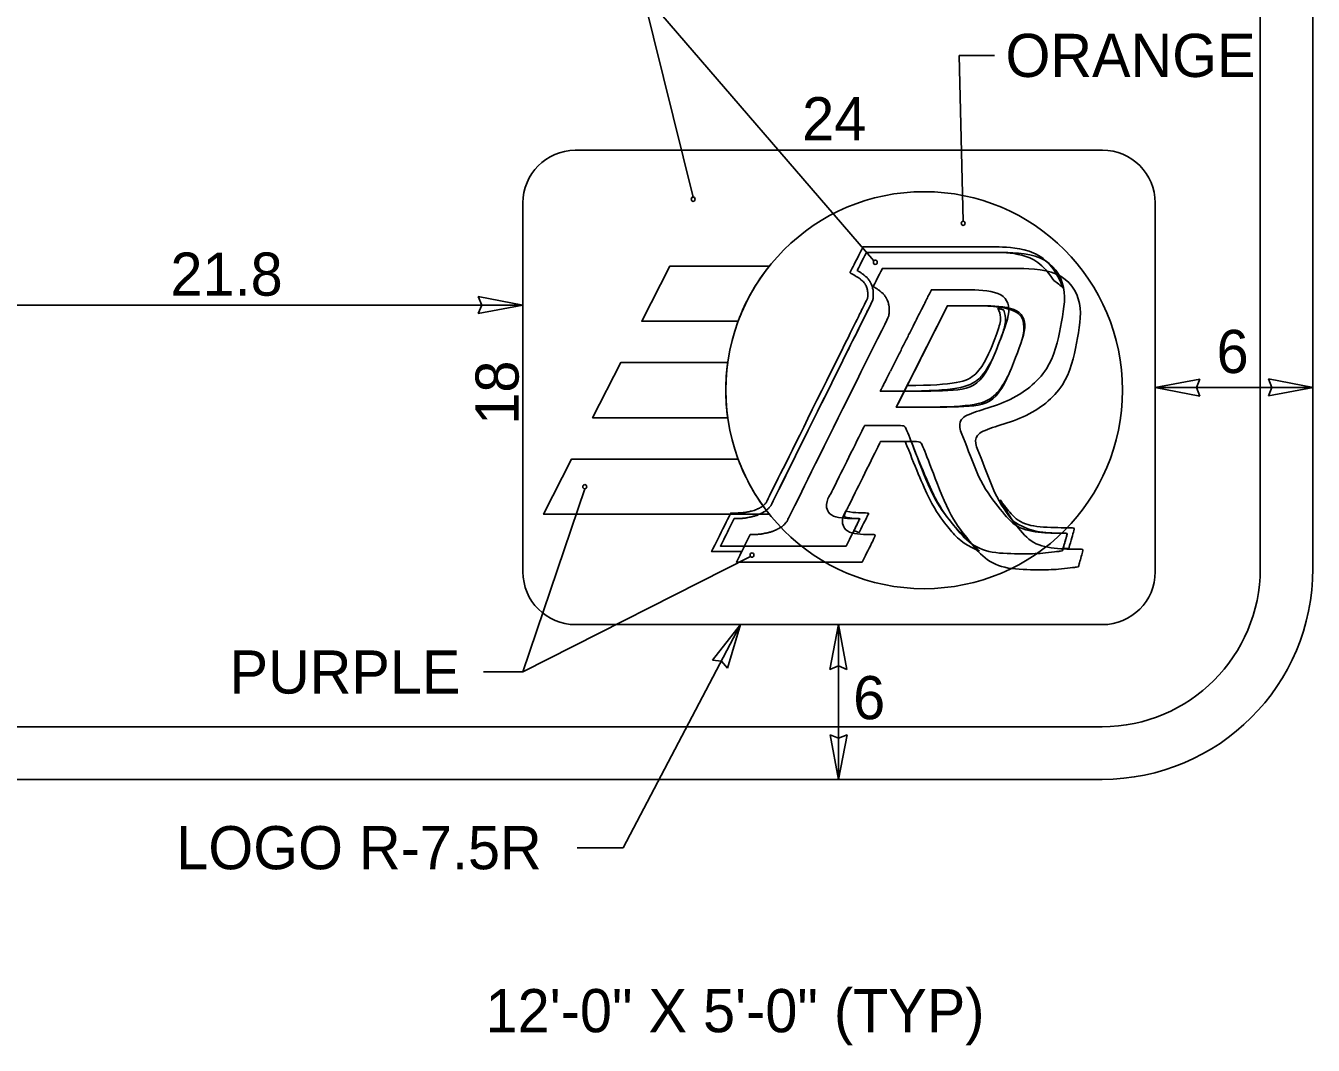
# Model space of a CAD drawing. Extents: x 319706 to 320449, y 1621775 to 1622117.
# Drawn here: x 320236.54 to 320278.32, y 1621842.48 to 1621875.55 of the extents above; entities that cross this region are included whole.
import ezdxf

# ---------------------------------------------------------------- set-up
doc = ezdxf.new("R2010")
doc.units = 0
for name, color, linetype in [('1', 7, 'Continuous'), ('52', 7, 'Continuous'), ('SignPanel', 7, 'Continuous')]:
    doc.layers.add(name, color=color, linetype=linetype)

msp = doc.modelspace()

# ---------------------------------------------------------------- linework, layer by layer
at = {"layer": '1'}
for p, q in [((320256.542, 1621876.645), (320258.197, 1621869.995)), ((320264.062, 1621867.926), (320256.542, 1621876.645)), ((320266.827, 1621874.588), (320267.975, 1621874.588)), ((320266.827, 1621874.588), (320266.96, 1621869.215)), ((320273.193, 1621863.82), (320278.323, 1621863.82)), ((320252.673, 1621854.589), (320254.68, 1621860.527)), ((320252.673, 1621854.589), (320260.06, 1621858.332)), ((320259.738, 1621856.125), (320255.927, 1621848.888)), ((320262.911, 1621851.105), (320262.911, 1621856.125)), ((320251.39, 1621854.589), (320252.673, 1621854.589)), ((320254.43, 1621848.888), (320255.927, 1621848.888))]:
    msp.add_line(p, q, dxfattribs=at)
for centre in [(320258.197, 1621869.924), (320266.96, 1621869.144), (320264.109, 1621867.877), (320254.68, 1621860.598), (320260.107, 1621858.381)]:
    msp.add_ellipse(centre, major_axis=(0, 0.0707), ratio=0.906668, dxfattribs=at)
at = {"layer": '52'}
for p, q in [((320252.673, 1621866.484), (320251.223, 1621866.764)), ((320251.223, 1621866.764), (320251.333, 1621866.484)), ((320251.333, 1621866.484), (320251.223, 1621866.214)), ((320251.223, 1621866.214), (320252.673, 1621866.484)), ((320274.643, 1621864.09), (320273.193, 1621863.82)), ((320274.533, 1621863.82), (320274.643, 1621864.09)), ((320278.323, 1621863.82), (320276.873, 1621864.1)), ((320276.873, 1621864.1), (320276.983, 1621863.82)), ((320273.193, 1621863.82), (320274.643, 1621863.54)), ((320274.643, 1621863.54), (320274.533, 1621863.82)), ((320276.983, 1621863.82), (320276.873, 1621863.55)), ((320276.873, 1621863.55), (320278.323, 1621863.82)), ((320258.824, 1621854.968), (320259.738, 1621856.125)), ((320259.738, 1621856.125), (320259.31, 1621854.712)), ((320262.911, 1621856.125), (320262.631, 1621854.675)), ((320263.181, 1621854.675), (320262.911, 1621856.125)), ((320259.114, 1621854.94), (320258.824, 1621854.968)), ((320259.31, 1621854.712), (320259.114, 1621854.94)), ((320262.631, 1621854.675), (320262.911, 1621854.785)), ((320262.911, 1621854.785), (320263.181, 1621854.675)), ((320262.911, 1621852.445), (320262.641, 1621852.555)), ((320262.641, 1621852.555), (320262.911, 1621851.105)), ((320262.911, 1621851.105), (320263.191, 1621852.555)), ((320263.191, 1621852.555), (320262.911, 1621852.445))]:
    msp.add_line(p, q, dxfattribs=at)
at = {"layer": 'SignPanel'}
for p, q in [((320276.602, 1621895.565), (320276.602, 1621857.945)), ((320278.312, 1621857.945), (320278.312, 1621895.565)), ((320254.363, 1621871.514), (320271.481, 1621871.514)), ((320252.673, 1621857.834), (320252.673, 1621869.805)), ((320273.193, 1621869.805), (320273.193, 1621857.834)), ((320252.673, 1621866.484), (320234.021, 1621866.484)), ((320263.056, 1621865.095), (320263.063, 1621865.11)), ((320263.223, 1621865.03), (320263.216, 1621865.015)), ((320265.273, 1621862.064), (320265.081, 1621862.064)), ((320259.862, 1621858.674), (320259.772, 1621858.496)), ((320271.481, 1621856.125), (320254.384, 1621856.125)), ((320271.472, 1621852.815), (320162.048, 1621852.815)), ((320162.048, 1621851.105), (320271.472, 1621851.105))]:
    msp.add_line(p, q, dxfattribs=at)
for points in [[(320260.669, 1621867.754), (320257.441, 1621867.754), (320256.53, 1621865.965), (320259.657, 1621865.965)], [(320267.307, 1621866.47), (320266.451, 1621866.47), (320264.789, 1621863.177), (320265.334, 1621863.177)], [(320259.319, 1621864.623), (320255.846, 1621864.623), (320254.934, 1621862.834), (320259.319, 1621862.834)], [(320259.657, 1621861.493), (320254.251, 1621861.493), (320253.34, 1621859.704), (320260.67, 1621859.704)]]:
    msp.add_lwpolyline(points, dxfattribs=at)
msp.add_circle((320265.695, 1621863.729), 6.438, dxfattribs=at)
for centre, radius, start, end in [((320254.382, 1621869.804), 1.71, 90.6597, 180), ((320271.481, 1621869.804), 1.71, 0, 90), ((320265.695, 1621863.729), 6.438, 141.3093, 159.6812), ((320268.931, 1621865.787), 1.786, 44.1751, 57.1095), ((320265.695, 1621863.729), 6.438, 172.0148, 187.9874), ((320265.695, 1621863.729), 6.438, 200.3256, 218.6989), ((320273.791, 1621863.128), 6.357, 207.7086, 215.0356), ((320263.593, 1621859.594), 0.486, 153.9516, 176.8436), ((320263.861, 1621860.105), 1.029, 244.3445, 254.3668), ((320269.318, 1621860.665), 2.825, 217.4324, 229.8152), ((320270.747, 1621863.158), 4.583, 263.2057, 265.4782), ((320254.382, 1621857.835), 1.71, 180, 270), ((320271.472, 1621857.945), 6.84, 270, 0), ((320271.472, 1621857.945), 5.13, 270, 0), ((320271.481, 1621857.835), 1.71, 270, 360)]:
    msp.add_arc(centre, radius, start, end, dxfattribs=at)
for points, degree in [([(320263.759, 1621862.583), (320263.759, 1621862.583), (320262.666, 1621860.376), (320262.666, 1621860.376), (320262.468, 1621860.054), (320262.61, 1621859.567), (320263.61, 1621859.567), (320263.61, 1621859.567), (320263.164, 1621858.674), (320263.164, 1621858.674), (320263.164, 1621858.674), (320259.084, 1621858.674), (320259.084, 1621858.674), (320259.084, 1621858.674), (320259.53, 1621859.567), (320259.53, 1621859.567), (320259.53, 1621859.567), (320259.657, 1621859.567), (320259.657, 1621859.567), (320259.657, 1621859.567), (320259.795, 1621859.573), (320259.795, 1621859.573), (320259.795, 1621859.573), (320259.91, 1621859.585), (320259.91, 1621859.585), (320259.91, 1621859.585), (320260.109, 1621859.627), (320260.109, 1621859.627), (320260.109, 1621859.627), (320260.26, 1621859.669), (320260.26, 1621859.669), (320260.26, 1621859.669), (320260.386, 1621859.724), (320260.386, 1621859.724), (320260.386, 1621859.724), (320260.477, 1621859.772), (320260.477, 1621859.772), (320260.477, 1621859.772), (320260.567, 1621859.826), (320260.567, 1621859.826), (320260.567, 1621859.826), (320260.658, 1621859.911), (320260.658, 1621859.911), (320260.658, 1621859.911), (320260.724, 1621859.995), (320260.724, 1621859.995), (320260.724, 1621859.995), (320260.748, 1621860.043), (320260.748, 1621860.043), (320260.748, 1621860.043), (320264.029, 1621866.653), (320264.029, 1621866.653), (320264.029, 1621866.653), (320264.041, 1621866.749), (320264.041, 1621866.749), (320264.041, 1621866.749), (320264.041, 1621866.839), (320264.041, 1621866.839), (320264.041, 1621866.839), (320264.041, 1621866.906), (320264.041, 1621866.906), (320264.041, 1621866.906), (320264.035, 1621866.99), (320264.035, 1621866.99), (320264.035, 1621866.99), (320264.01, 1621867.093), (320264.01, 1621867.093), (320264.01, 1621867.093), (320263.968, 1621867.201), (320263.968, 1621867.201), (320263.968, 1621867.201), (320263.926, 1621867.273), (320263.926, 1621867.273), (320263.926, 1621867.273), (320263.847, 1621867.376), (320263.847, 1621867.376), (320263.847, 1621867.376), (320263.739, 1621867.467), (320263.739, 1621867.467), (320263.739, 1621867.467), (320263.631, 1621867.545), (320263.631, 1621867.545), (320263.631, 1621867.545), (320263.522, 1621867.611), (320263.522, 1621867.611), (320263.522, 1621867.611), (320263.818, 1621868.196), (320263.818, 1621868.196), (320263.818, 1621868.196), (320267.829, 1621868.196), (320267.829, 1621868.196), (320269.65, 1621868.196), (320270.38, 1621867.092), (320270.125, 1621865.8), (320269.842, 1621864.369), (320268.469, 1621863.249), (320266.6, 1621862.922), (320267.009, 1621862.159), (320267.498, 1621860.697), (320268.197, 1621859.826), (320268.672, 1621859.234), (320269.499, 1621859.09), (320270.343, 1621859.09), (320270.343, 1621859.09), (320270.18, 1621858.519), (320270.18, 1621858.519), (320270.18, 1621858.519), (320270.068, 1621858.503), (320270.068, 1621858.503), (320269.604, 1621858.441), (320269.306, 1621858.425), (320268.963, 1621858.425), (320267.827, 1621858.425), (320267.129, 1621858.752), (320266.593, 1621859.421), (320265.968, 1621860.199), (320265.365, 1621861.856), (320265.064, 1621862.583), (320265.064, 1621862.583), (320263.759, 1621862.583), (320263.759, 1621862.583)], 3), ([(320263.063, 1621865.11), (320263.526, 1621866.043), (320263.855, 1621866.705), (320263.855, 1621866.705), (320263.855, 1621866.705), (320263.862, 1621866.76), (320263.862, 1621866.76), (320263.862, 1621866.76), (320263.862, 1621866.839), (320263.862, 1621866.839), (320263.862, 1621866.839), (320263.862, 1621866.899), (320263.862, 1621866.899), (320263.862, 1621866.899), (320263.857, 1621866.963), (320263.857, 1621866.963), (320263.857, 1621866.963), (320263.839, 1621867.04), (320263.839, 1621867.04), (320263.839, 1621867.04), (320263.807, 1621867.123), (320263.807, 1621867.123), (320263.807, 1621867.123), (320263.777, 1621867.173), (320263.777, 1621867.173), (320263.777, 1621867.173), (320263.717, 1621867.252), (320263.717, 1621867.252), (320263.717, 1621867.252), (320263.629, 1621867.325), (320263.629, 1621867.325), (320263.629, 1621867.325), (320263.532, 1621867.396), (320263.532, 1621867.396), (320263.532, 1621867.396), (320263.288, 1621867.544), (320263.288, 1621867.544), (320263.288, 1621867.544), (320263.708, 1621868.375), (320263.708, 1621868.375), (320263.708, 1621868.375), (320267.829, 1621868.375), (320267.829, 1621868.375), (320269.116, 1621868.375), (320269.91, 1621867.814), (320270.212, 1621867.032)], 3), ([(320263.223, 1621865.03), (320263.686, 1621865.963), (320264.029, 1621866.653), (320264.029, 1621866.653), (320264.029, 1621866.653), (320264.041, 1621866.749), (320264.041, 1621866.749), (320264.041, 1621866.749), (320264.041, 1621866.839), (320264.041, 1621866.839), (320264.041, 1621866.839), (320264.041, 1621866.906), (320264.041, 1621866.906), (320264.041, 1621866.906), (320264.035, 1621866.99), (320264.035, 1621866.99), (320264.035, 1621866.99), (320264.01, 1621867.093), (320264.01, 1621867.093), (320264.01, 1621867.093), (320263.968, 1621867.201), (320263.968, 1621867.201), (320263.968, 1621867.201), (320263.926, 1621867.273), (320263.926, 1621867.273), (320263.926, 1621867.273), (320263.847, 1621867.376), (320263.847, 1621867.376), (320263.847, 1621867.376), (320263.739, 1621867.467), (320263.739, 1621867.467), (320263.739, 1621867.467), (320263.631, 1621867.545), (320263.631, 1621867.545), (320263.631, 1621867.545), (320263.522, 1621867.611), (320263.522, 1621867.611), (320263.522, 1621867.611), (320263.818, 1621868.196), (320263.818, 1621868.196), (320263.818, 1621868.196), (320267.829, 1621868.196), (320267.829, 1621868.196), (320269.65, 1621868.196), (320270.38, 1621867.092), (320270.125, 1621865.8), (320269.842, 1621864.369), (320268.469, 1621863.249), (320266.6, 1621862.922), (320267.009, 1621862.159), (320267.498, 1621860.697), (320268.197, 1621859.826), (320268.672, 1621859.234), (320269.499, 1621859.09), (320270.343, 1621859.09), (320270.343, 1621859.09), (320270.18, 1621858.519), (320270.18, 1621858.519), (320270.18, 1621858.519), (320270.068, 1621858.503), (320270.068, 1621858.503), (320269.604, 1621858.441), (320269.306, 1621858.425), (320268.963, 1621858.425), (320267.827, 1621858.425), (320267.129, 1621858.752), (320266.593, 1621859.421), (320265.968, 1621860.199), (320265.365, 1621861.856), (320265.064, 1621862.583), (320265.064, 1621862.583), (320263.759, 1621862.583), (320263.759, 1621862.583)], 3), ([(320269.901, 1621867.287), (320269.552, 1621867.836), (320268.868, 1621868.196), (320267.829, 1621868.196), (320267.829, 1621868.196), (320263.818, 1621868.196), (320263.818, 1621868.196), (320263.818, 1621868.196), (320263.522, 1621867.611), (320263.522, 1621867.611), (320263.522, 1621867.611), (320263.631, 1621867.545), (320263.631, 1621867.545), (320263.631, 1621867.545), (320263.739, 1621867.467), (320263.739, 1621867.467), (320263.739, 1621867.467), (320263.847, 1621867.376), (320263.847, 1621867.376), (320263.847, 1621867.376), (320263.926, 1621867.273), (320263.926, 1621867.273), (320263.926, 1621867.273), (320263.968, 1621867.201), (320263.968, 1621867.201), (320263.968, 1621867.201), (320264.01, 1621867.093), (320264.01, 1621867.093), (320264.01, 1621867.093), (320264.035, 1621866.99), (320264.035, 1621866.99), (320264.035, 1621866.99), (320264.041, 1621866.906), (320264.041, 1621866.906), (320264.041, 1621866.906), (320264.041, 1621866.839), (320264.041, 1621866.839), (320264.041, 1621866.839), (320264.041, 1621866.749), (320264.041, 1621866.749), (320264.041, 1621866.749), (320264.029, 1621866.653), (320264.029, 1621866.653), (320264.029, 1621866.653), (320263.686, 1621865.963), (320263.223, 1621865.03)], 3), ([(320264.278, 1621862.064), (320264.278, 1621862.064), (320263.185, 1621859.858), (320263.185, 1621859.858), (320262.986, 1621859.536), (320263.129, 1621859.048), (320264.129, 1621859.048), (320264.129, 1621859.048), (320263.683, 1621858.156), (320263.683, 1621858.156), (320263.683, 1621858.156), (320259.602, 1621858.156), (320259.602, 1621858.156), (320259.602, 1621858.156), (320260.049, 1621859.048), (320260.049, 1621859.048), (320260.049, 1621859.048), (320260.175, 1621859.048), (320260.175, 1621859.048), (320260.175, 1621859.048), (320260.314, 1621859.055), (320260.314, 1621859.055), (320260.314, 1621859.055), (320260.428, 1621859.066), (320260.428, 1621859.066), (320260.428, 1621859.066), (320260.628, 1621859.108), (320260.628, 1621859.108), (320260.628, 1621859.108), (320260.778, 1621859.151), (320260.778, 1621859.151), (320260.778, 1621859.151), (320260.905, 1621859.205), (320260.905, 1621859.205), (320260.905, 1621859.205), (320260.995, 1621859.253), (320260.995, 1621859.253), (320260.995, 1621859.253), (320261.086, 1621859.308), (320261.086, 1621859.308), (320261.086, 1621859.308), (320261.176, 1621859.392), (320261.176, 1621859.392), (320261.176, 1621859.392), (320261.243, 1621859.476), (320261.243, 1621859.476), (320261.243, 1621859.476), (320261.266, 1621859.525), (320261.266, 1621859.525), (320261.266, 1621859.525), (320264.547, 1621866.134), (320264.547, 1621866.134), (320264.547, 1621866.134), (320264.559, 1621866.23), (320264.559, 1621866.23), (320264.559, 1621866.23), (320264.559, 1621866.32), (320264.559, 1621866.32), (320264.559, 1621866.32), (320264.559, 1621866.387), (320264.559, 1621866.387), (320264.559, 1621866.387), (320264.553, 1621866.471), (320264.553, 1621866.471), (320264.553, 1621866.471), (320264.529, 1621866.574), (320264.529, 1621866.574), (320264.529, 1621866.574), (320264.487, 1621866.683), (320264.487, 1621866.683), (320264.487, 1621866.683), (320264.445, 1621866.755), (320264.445, 1621866.755), (320264.445, 1621866.755), (320264.366, 1621866.858), (320264.366, 1621866.858), (320264.366, 1621866.858), (320264.258, 1621866.948), (320264.258, 1621866.948), (320264.258, 1621866.948), (320264.149, 1621867.026), (320264.149, 1621867.026), (320264.149, 1621867.026), (320264.041, 1621867.092), (320264.041, 1621867.092), (320264.041, 1621867.092), (320264.336, 1621867.678), (320264.336, 1621867.678), (320264.336, 1621867.678), (320268.348, 1621867.678), (320268.348, 1621867.678), (320270.168, 1621867.678), (320270.899, 1621866.573), (320270.644, 1621865.281), (320270.361, 1621863.85), (320268.988, 1621862.73), (320267.119, 1621862.403), (320267.528, 1621861.641), (320268.017, 1621860.178), (320268.716, 1621859.307), (320269.191, 1621858.716), (320270.018, 1621858.571), (320270.862, 1621858.571), (320270.862, 1621858.571), (320270.698, 1621858), (320270.698, 1621858), (320270.698, 1621858), (320270.586, 1621857.984), (320270.586, 1621857.984), (320270.123, 1621857.922), (320269.824, 1621857.907), (320269.482, 1621857.907), (320268.346, 1621857.907), (320267.648, 1621858.233), (320267.111, 1621858.902), (320266.487, 1621859.68), (320265.884, 1621861.338), (320265.583, 1621862.064), (320265.583, 1621862.064), (320264.278, 1621862.064), (320264.278, 1621862.064)], 3), ([(320264.592, 1621864.332), (320264.402, 1621863.957), (320264.27, 1621863.696), (320264.27, 1621863.696), (320264.27, 1621863.696), (320264.815, 1621863.696), (320264.815, 1621863.696), (320266.604, 1621863.696), (320267.57, 1621863.828), (320268.171, 1621865.384), (320268.588, 1621866.462), (320268.126, 1621866.988), (320266.788, 1621866.988), (320266.788, 1621866.988), (320265.932, 1621866.988), (320265.932, 1621866.988)], 3), ([(320265.932, 1621866.988), (320265.932, 1621866.988), (320265.083, 1621865.307), (320264.599, 1621864.347)], 2), ([(320266.451, 1621866.47), (320266.451, 1621866.47), (320264.789, 1621863.177), (320264.789, 1621863.177), (320264.789, 1621863.177), (320265.334, 1621863.177), (320265.334, 1621863.177), (320267.123, 1621863.177), (320268.088, 1621863.309), (320268.69, 1621864.865), (320269.107, 1621865.943), (320268.645, 1621866.47), (320267.307, 1621866.47), (320267.307, 1621866.47), (320266.451, 1621866.47), (320266.451, 1621866.47)], 3), ([(320265.142, 1621863.877), (320266.699, 1621863.895), (320267.477, 1621864.083), (320268.004, 1621865.448), (320268.165, 1621865.863), (320268.196, 1621866.171), (320268.084, 1621866.388)], 3), ([(320265.334, 1621863.177), (320267.123, 1621863.177), (320268.088, 1621863.309), (320268.69, 1621864.865), (320269.107, 1621865.943), (320268.645, 1621866.47), (320267.307, 1621866.47)], 3), ([(320268.084, 1621866.388), (320268.155, 1621866.369), (320268.222, 1621866.348), (320268.283, 1621866.323)], 2), ([(320268.283, 1621866.323), (320268.356, 1621866.079), (320268.319, 1621865.766), (320268.171, 1621865.384), (320267.597, 1621863.898), (320266.69, 1621863.711), (320265.051, 1621863.697)], 3), ([(320259.772, 1621858.496), (320259.202, 1621858.496), (320258.794, 1621858.496), (320258.794, 1621858.496), (320258.794, 1621858.496), (320259.419, 1621859.746), (320259.419, 1621859.746), (320259.419, 1621859.746), (320259.652, 1621859.746), (320259.652, 1621859.746), (320259.652, 1621859.746), (320259.782, 1621859.752), (320259.782, 1621859.752), (320259.782, 1621859.752), (320259.882, 1621859.762), (320259.882, 1621859.762), (320259.882, 1621859.762), (320260.066, 1621859.801), (320260.066, 1621859.801), (320260.066, 1621859.801), (320260.2, 1621859.838), (320260.2, 1621859.838), (320260.2, 1621859.838), (320260.308, 1621859.885), (320260.308, 1621859.885), (320260.308, 1621859.885), (320260.389, 1621859.928), (320260.389, 1621859.928), (320260.389, 1621859.928), (320260.459, 1621859.97), (320260.459, 1621859.97), (320260.459, 1621859.97), (320260.526, 1621860.032), (320260.526, 1621860.032), (320260.526, 1621860.032), (320260.572, 1621860.091), (320260.572, 1621860.091), (320260.572, 1621860.091), (320260.587, 1621860.122), (320260.587, 1621860.122), (320260.587, 1621860.122), (320262.084, 1621863.137), (320263.056, 1621865.095)], 3), ([(320263.759, 1621862.583), (320263.759, 1621862.583), (320262.666, 1621860.376), (320262.666, 1621860.376), (320262.468, 1621860.054), (320262.61, 1621859.567), (320263.61, 1621859.567), (320263.61, 1621859.567), (320263.164, 1621858.674), (320263.164, 1621858.674), (320263.164, 1621858.674), (320259.084, 1621858.674), (320259.084, 1621858.674), (320259.084, 1621858.674), (320259.53, 1621859.567), (320259.53, 1621859.567), (320259.53, 1621859.567), (320259.657, 1621859.567), (320259.657, 1621859.567), (320259.657, 1621859.567), (320259.795, 1621859.573), (320259.795, 1621859.573), (320259.795, 1621859.573), (320259.91, 1621859.585), (320259.91, 1621859.585), (320259.91, 1621859.585), (320260.109, 1621859.627), (320260.109, 1621859.627), (320260.109, 1621859.627), (320260.26, 1621859.669), (320260.26, 1621859.669), (320260.26, 1621859.669), (320260.386, 1621859.724), (320260.386, 1621859.724), (320260.386, 1621859.724), (320260.477, 1621859.772), (320260.477, 1621859.772), (320260.477, 1621859.772), (320260.567, 1621859.826), (320260.567, 1621859.826), (320260.567, 1621859.826), (320260.658, 1621859.911), (320260.658, 1621859.911), (320260.658, 1621859.911), (320260.724, 1621859.995), (320260.724, 1621859.995), (320260.724, 1621859.995), (320260.748, 1621860.043), (320260.748, 1621860.043), (320260.748, 1621860.043), (320262.244, 1621863.058), (320263.216, 1621865.015)], 3), ([(320263.216, 1621865.015), (320262.244, 1621863.058), (320260.748, 1621860.043), (320260.748, 1621860.043), (320260.748, 1621860.043), (320260.724, 1621859.995), (320260.724, 1621859.995), (320260.724, 1621859.995), (320260.658, 1621859.911), (320260.658, 1621859.911), (320260.658, 1621859.911), (320260.567, 1621859.826), (320260.567, 1621859.826), (320260.567, 1621859.826), (320260.477, 1621859.772), (320260.477, 1621859.772), (320260.477, 1621859.772), (320260.386, 1621859.724), (320260.386, 1621859.724), (320260.386, 1621859.724), (320260.26, 1621859.669), (320260.26, 1621859.669), (320260.26, 1621859.669), (320260.109, 1621859.627), (320260.109, 1621859.627), (320260.109, 1621859.627), (320259.91, 1621859.585), (320259.91, 1621859.585), (320259.91, 1621859.585), (320259.795, 1621859.573), (320259.795, 1621859.573), (320259.795, 1621859.573), (320259.657, 1621859.567), (320259.657, 1621859.567), (320259.657, 1621859.567), (320259.53, 1621859.567), (320259.53, 1621859.567), (320259.53, 1621859.567), (320259.084, 1621858.674), (320259.084, 1621858.674), (320259.084, 1621858.674), (320259.402, 1621858.674), (320259.862, 1621858.674)], 3), ([(320265.051, 1621863.697), (320265.08, 1621863.754), (320265.11, 1621863.814), (320265.142, 1621863.877)], 2), ([(320265.081, 1621862.064), (320265.382, 1621861.308), (320265.907, 1621859.99), (320266.453, 1621859.309), (320266.738, 1621858.954), (320267.077, 1621858.685), (320267.495, 1621858.507)], 3), ([(320267.075, 1621858.949), (320266.898, 1621859.081), (320266.74, 1621859.238), (320266.593, 1621859.421), (320266.09, 1621860.047), (320265.602, 1621861.242), (320265.273, 1621862.064)], 3), ([(320268.163, 1621860.172), (320268.22, 1621860.09), (320268.278, 1621860.012), (320268.337, 1621859.938), (320268.769, 1621859.399), (320269.515, 1621859.269), (320270.58, 1621859.269), (320270.58, 1621859.269), (320270.463, 1621858.859), (320270.386, 1621858.589)], 3), ([(320263.157, 1621859.807), (320263.331, 1621859.769), (320263.572, 1621859.746), (320263.9, 1621859.746), (320263.9, 1621859.746), (320263.741, 1621859.428), (320263.583, 1621859.113)], 3), ([(320263.415, 1621859.177), (320263.517, 1621859.38), (320263.61, 1621859.567), (320263.61, 1621859.567), (320263.41, 1621859.567), (320263.244, 1621859.587), (320263.108, 1621859.62)], 3), ([(320270.205, 1621858.607), (320270.251, 1621858.767), (320270.343, 1621859.09), (320270.343, 1621859.09), (320269.698, 1621859.09), (320269.062, 1621859.174), (320268.586, 1621859.479)], 3)]:
    msp.add_open_spline(points, degree=degree, dxfattribs=at)

# ---------------------------------------------------------------- texts
at = {"layer": '1'}
for s, p in [('ORANGE', (320268.335, 1621873.888)), ('24', (320261.734, 1621871.834)), ('21.8', (320241.231, 1621866.794)), ('6', (320275.185, 1621864.285)), ('PURPLE', (320243.152, 1621853.889)), ('6', (320263.389, 1621853.057)), ('LOGO R-7.5R', (320241.421, 1621848.191)), ('12\'-0" X 5\'-0" (TYP)', (320251.459, 1621842.905))]:
    msp.add_text(s, height=1.4, dxfattribs=at).set_placement(p)
msp.add_text('18', height=1.4, rotation=90, dxfattribs=at).set_placement((320252.532, 1621862.608))

doc.saveas('drawing.dxf')
